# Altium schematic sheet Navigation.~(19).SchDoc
size A
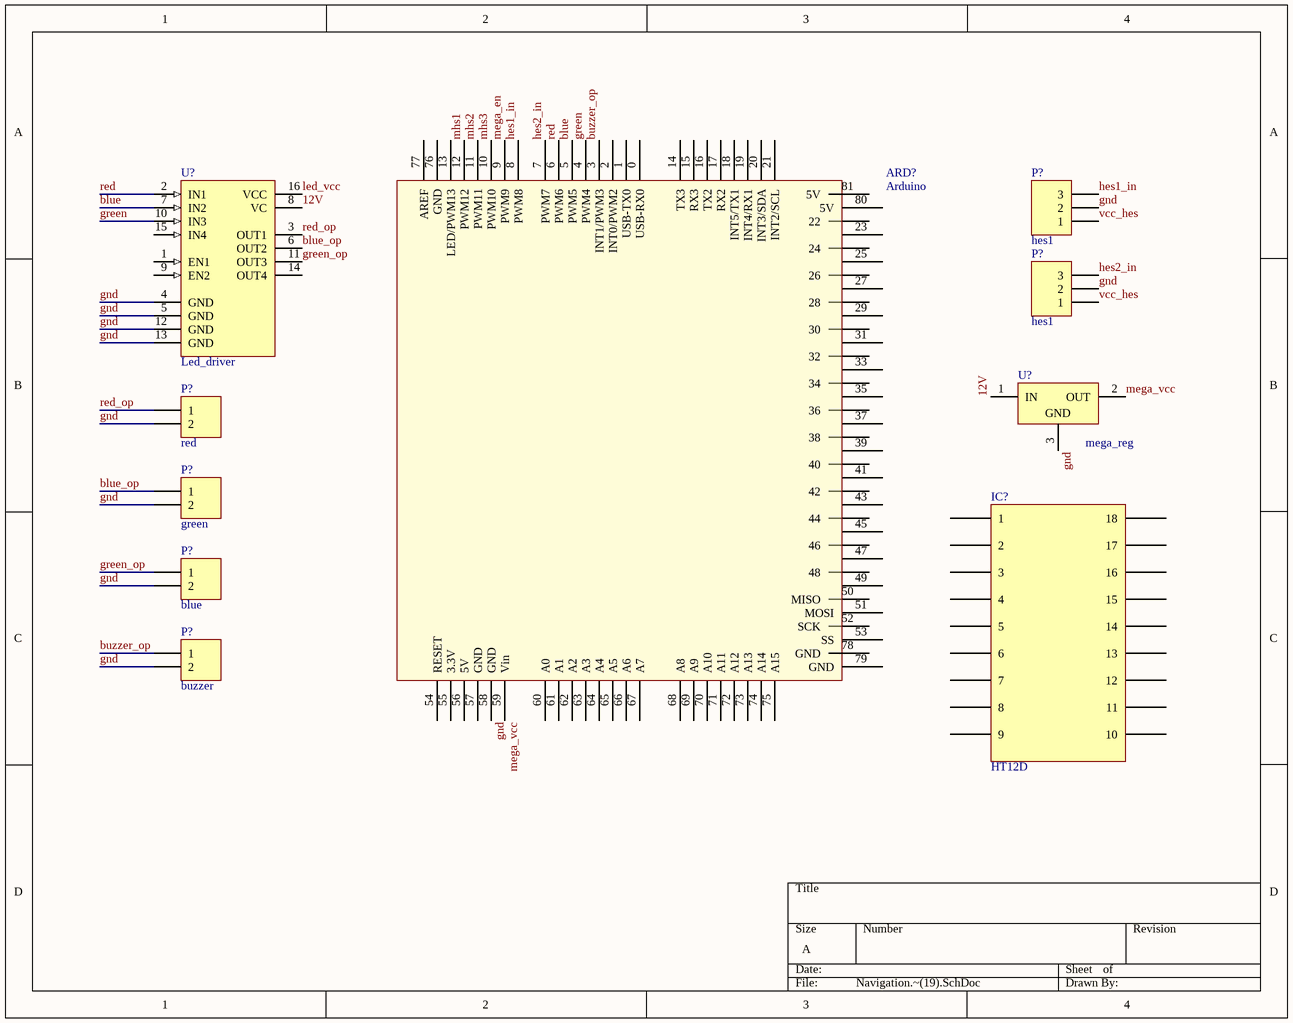
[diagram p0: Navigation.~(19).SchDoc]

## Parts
(Parts that share a designator on the sheet are numbered #1, #2 ... from top to bottom, then left to right.)
ARD?  Arduino  [Arduino]
IC?  HT12D  [HT12D]
P?#1  hes1  [HDR1X3H]
P?#2  hes1  [HDR1X3H]
P?#3  red  [HDR1X2H]
P?#4  green  [HDR1X2H]
P?#5  blue  [HDR1X2H]
P?#6  buzzer  [HDR1X2H]
U?#1  Led_driver  [DIP16]
U?#2  mega_reg  [TO220ABN]

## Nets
12V: U?#1.8(VC) U?#2.1(IN)
blue: ARD?.5(PWM5) U?#1.7(IN2)
blue_op: P?#4.1 U?#1.6(OUT2)
buzzer_op: ARD?.3(INT1/PWM3) P?#6.1
gnd: ARD?.58(GND) P?#1.2 P?#2.2 P?#3.2 P?#4.2 P?#5.2 P?#6.2 U?#1.4(GND) U?#1.5(GND) U?#1.12(GND) U?#1.13(GND) U?#2.3(GND)
green: ARD?.4(PWM4) U?#1.10(IN3)
green_op: P?#5.1 U?#1.11(OUT3)
hes1_in: ARD?.8(PWM8) P?#1.3
hes2_in: ARD?.7(PWM7) P?#2.3
led_vcc: U?#1.16(VCC)
mega_en: ARD?.9(PWM9)
mega_vcc: ARD?.59(Vin) U?#2.2(OUT)
mhs1: ARD?.12(PWM12)
mhs2: ARD?.11(PWM11)
mhs3: ARD?.10(PWM10)
red: ARD?.6(PWM6) U?#1.2(IN1)
red_op: P?#3.1 U?#1.3(OUT1)
vcc_hes: P?#1.1 P?#2.1

Not connected (* = marked no-connect by the designer): ARD? 0(USB-RX0) 1(USB-TX0) 2(INT0/PWM2) 13(LED/PWM13) 14(TX3) 15(RX3) 16(TX2) 17(RX2) 18(INT5/TX1) 19(INT4/RX1) 20(INT3/SDA) 21(INT2/SCL) 22 23 24 25 26 27 28 29 30 31 32 33 34 35 36 37 38 39 40 41 42 43 44 45 46 47 48 49 50(MISO) 51(MOSI) 52(SCK) 53(SS) 54(RESET) 55(3.3V) 56(5V) 57(GND) 60(A0) 61(A1) 62(A2) 63(A3) 64(A4) 65(A5) 66(A6) 67(A7) 68(A8) 69(A9) 70(A10) 71(A11) 72(A12) 73(A13) 74(A14) 75(A15) 76(GND) 77(AREF) 78(GND) 79(GND) 80(5V) 81(5V); IC? 1 2 3 4 5 6 7 8 9 10 11 12 13 14 15 16 17 18; U?#1 1(EN1) 9(EN2) 14(OUT4) 15(IN4)

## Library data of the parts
P?#1 P?#2 = Header 3H: Header, 3-Pin, Right Angle
P?#3-P?#6 = Header 2H: Header, 2-Pin, Right Angle
U?#1 = L293D: Push-Pull Four Channel Driver With Diode
U?#2 = L7805CV: Positive Voltage Regulator; Note: Tab is connected to pin 3 (GND).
